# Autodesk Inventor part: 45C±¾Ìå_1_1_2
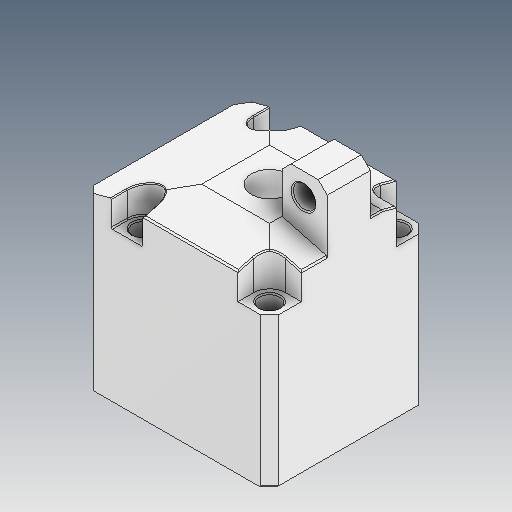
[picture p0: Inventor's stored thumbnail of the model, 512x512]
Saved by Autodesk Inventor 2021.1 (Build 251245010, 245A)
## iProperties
Created: 2021-05
Part Number: 45C±¾Ìå_1_1_2
Material: Ogólny
Document SubType Name: Modeling
Designer: user
Density: 1 g/cm^3
Appearance: Domyślna
Author: user
Revision Number: ÈÎºÎ
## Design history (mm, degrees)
feature "ÊäÈë1"
node "Bryła1"
